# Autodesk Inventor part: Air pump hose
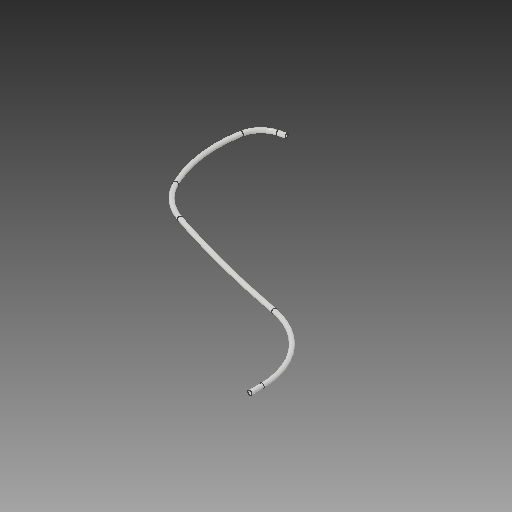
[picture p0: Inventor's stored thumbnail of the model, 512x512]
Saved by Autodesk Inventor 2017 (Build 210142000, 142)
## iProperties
Created: 2020-03
Part Number: Air pump hose
Material: Generic
Document SubType Name: Modeling
Designer: user
Density: 1 g/cm^3
Appearance: Default
Mass: 8.0647 g
Surface Area: 269.072 cm^2
Volume: 8.0647 cm^3
Author: user
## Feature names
1. Sweep1
## Parameters: d0 = 342.232 mm, d1 = 32.652 mm, d2 = 0, d5 = 12 mm, d6 = 28.83633 mm, d7 = 6 mm, d8 = 7.2 mm, d9 = 0, d10 = 0
